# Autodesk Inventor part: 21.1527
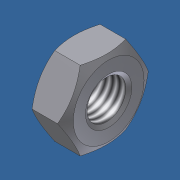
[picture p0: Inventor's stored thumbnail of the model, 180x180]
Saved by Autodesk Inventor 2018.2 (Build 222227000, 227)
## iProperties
Created: 2006-02
Part Number: 21.1527
Material: Steel, Mild
Description: M10 HEX NUT
Document SubType Name: Modeling
Standard: DIN 934
Designer: Andy Moles
Standards Organization: DIN
Language: en-US
Size Designation: M10
Categories: <MemberInstance><Categories><Category DisplayName="Fasteners" InternalName="e4da775c-781d-43d5-af7c-5136215cf5a6" Mnemonic="FSTN"><Category DisplayName="Nuts" I
Mass: 11.7411 g
Surface Area: 9.86681 cm^2
Volume: 1.49568 cm^3
Density: 7.85 g/cm^3
Appearance: Zinc
Author: Andy Moles
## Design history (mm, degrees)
sketch "Sketch1"
  geometry: L1 (-9.815, 0)-(-4.907, 8.5); L2 (-4.907, 8.5)-(4.907, 8.5); L3 (4.907, 8.5)-(9.815, 0); L4 (9.815, 0)-(4.907, -8.5); L5 (4.907, -8.5)-(-4.907, -8.5); L6 (-4.907, -8.5)-(-9.815, 0); 2 further points
  constraints: 12 end point, 1 coincident, 1 horizontal, 11 other
  dimensions: "d0" = 19.62991 distance of L3.end L1.start (= 1.1547 x SW)
extrude "Body" new body sketch "Sketch1" distance "d1" = 8 (= KOH); taper "d2" = 0 deg
sketch "Sketch2"
  geometry: L1 (0, 4.907)-(0, 9.815) reference; L2 (0, 9.815)-(8, 9.815) reference; L3 (8, 4.907)-(8, 9.815) reference; L4 (-0.8, 0)-(10.4, 0) reference; L5 (1.25, 9.815)-(0, 7.65); L6 (6.75, 9.815)-(8, 7.65)
  constraints: 4 end point, 4 point on line
  dimensions: "d3" = 30 deg angle of L1 L5 (= ANG1); "d4" = 30 deg angle of L3 L6 (= ANG2); "d5" = 15.3 diameter of L5.end L4 (= SW0); "d6" = 15.3 diameter of L6.end L4 (= SW01)
revolve "Chamfer1" sketch "Sketch2" stored, may be unused: angle "d7" = 90 deg
sketch "Sketch3"
  geometry: 4 further points
  constraints: 1 coincident, 1 other
hole "Thread" sketch "Sketch3" at (0, 0) diameter "d25" = 8.376; stored, may be unused: countersink angle "d29" = 82 deg, drill point angle "d31" = 118 deg; dims "d26" = 6, "d27" = 4, "d28" = 2, "d30" = 8
workaxis "Work Axis1"
workplane "Work Plane1"
body "Solid1"
chamfer "Chamfer2" distance "d8" = 0.8119 (= -0.5 x GD1 + 0.5 x NND); stored, may be unused: angle "d9" = 30 deg, second distance "d40" = 0.8119 (= -0.5 x GD1 + 0.5 x NND)
chamfer "Chamfer3" distance "d10" = 0.8119 (= -0.5 x GD1 + 0.5 x NND); stored, may be unused: angle "d11" = 30 deg, second distance "d41" = 0.8119 (= -0.5 x GD1 + 0.5 x NND)
other parameters: "ANG1" = 30 deg [user parameter; used in 1 equation term], "ANG2" = 30 deg [user parameter; used in 1 equation term], "KOH" = 8 [user parameter; used in 1 equation term], "SW" = 17 [user parameter; used in 2 equation terms], "SW0" = 15.3 (= SW01) [user parameter; used in 1 equation term], "SW01" = 15.3 [user parameter; used in 2 equation terms], "GD1" = 8.3762 (computed from THREADDIA, PTC, TOA) [user parameter; used in 4 equation terms], "d13" = 0, "d14" = 0, "d39" = 0, "d42" = 0, "GUL" = 0.8119 (= 0.541266 x PTC) [user parameter], "TPU" = 6.66667 (computed from PTC) [user parameter], "TOA" = 30 deg [user parameter; used in 1 equation term], "PTC" = 1.5 [user parameter; used in 4 equation terms], "E0" = 19.635 (= 1.155 x SW) [user parameter], "GAL" = 0.8119 (= 0.541266 x PTC) [user parameter]
